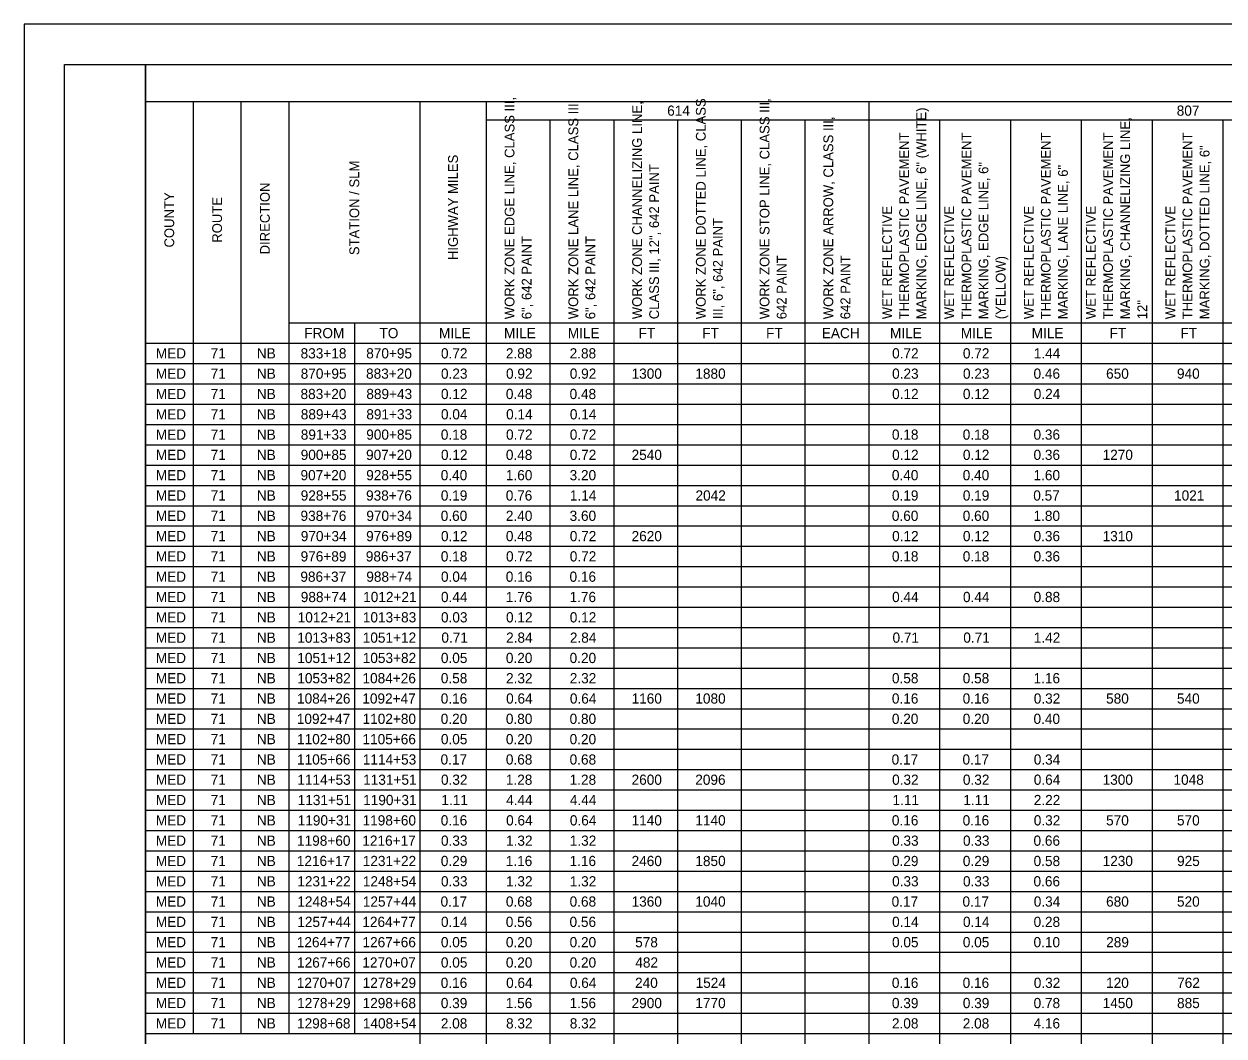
# Model space of a CAD drawing. Extents: x 0 to 34, y 0 to 22.
# Drawn here: x 0 to 14.83, y 9.5 to 22 of the extents above; entities that cross this region are included whole.
import ezdxf

# ---------------------------------------------------------------- set-up
doc = ezdxf.new("R2010")
doc.units = 0
for name, color, linetype in [('SH_Border', 7, 'Continuous'), ('SH_Cut_Line', 7, 'Continuous'), ('SH_Text', 7, 'Continuous')]:
    doc.layers.add(name, color=color, linetype=linetype)

msp = doc.modelspace()

# ---------------------------------------------------------------- linework, layer by layer
at = {"layer": 'SH_Border'}
for points in [[(0.5, 21.5), (1.5, 21.5), (1.5, 0.5), (0.5, 0.5)], [(1.5, 21.5), (33.5, 21.5), (33.5, 0.5), (1.5, 0.5)]]:
    msp.add_lwpolyline(points, close=True, dxfattribs=at)
at = {"layer": 'SH_Cut_Line'}
msp.add_lwpolyline([(0, 0), (34, 0), (34, 22), (0, 22)], close=True, dxfattribs=at)
at = {"layer": 'SH_Text'}
for p, q in [((1.5, 21.5), (32, 21.5)), ((1.5, 21.5), (1.5, 0.5)), ((1.5, 21.044), (32, 21.044)), ((2.091, 21.044), (2.091, 9.529)), ((2.682, 21.044), (2.682, 9.529)), ((3.273, 21.044), (3.273, 18.308)), ((4.893, 21.044), (4.893, 0.5)), ((5.713, 21.044), (5.713, 0.5)), ((10.441, 21.044), (10.441, 0.5)), ((5.713, 20.816), (32, 20.816)), ((6.501, 20.816), (6.501, 0.5)), ((7.289, 20.816), (7.289, 0.5)), ((8.077, 20.816), (8.077, 0.5)), ((8.865, 20.816), (8.865, 0.5)), ((9.653, 20.816), (9.653, 0.5)), ((11.316, 20.816), (11.316, 0.5)), ((12.192, 20.816), (12.192, 0.5)), ((13.067, 20.816), (13.067, 0.5)), ((13.943, 20.816), (13.943, 0.5)), ((14.818, 20.816), (14.818, 0.5)), ((3.273, 18.308), (32, 18.308)), ((3.273, 18.308), (3.273, 18.057)), ((4.083, 18.308), (4.083, 9.529)), ((1.5, 18.057), (32, 18.057)), ((3.273, 18.057), (3.273, 9.529)), ((1.5, 17.806), (32, 17.806)), ((1.5, 17.555), (32, 17.555)), ((1.5, 17.305), (32, 17.305)), ((1.5, 17.054), (32, 17.054)), ((1.5, 16.803), (32, 16.803)), ((1.5, 16.552), (32, 16.552)), ((1.5, 16.301), (32, 16.301)), ((1.5, 16.05), (32, 16.05)), ((1.5, 15.8), (32, 15.8)), ((1.5, 15.549), (32, 15.549)), ((1.5, 15.298), (32, 15.298)), ((1.5, 15.047), (32, 15.047)), ((1.5, 14.796), (32, 14.796)), ((1.5, 14.546), (32, 14.546)), ((1.5, 14.295), (32, 14.295)), ((1.5, 14.044), (32, 14.044)), ((1.5, 13.793), (32, 13.793)), ((1.5, 13.542), (32, 13.542)), ((1.5, 13.292), (32, 13.292)), ((1.5, 13.041), (32, 13.041)), ((1.5, 12.79), (32, 12.79)), ((1.5, 12.539), (32, 12.539)), ((1.5, 12.288), (32, 12.288)), ((1.5, 12.037), (32, 12.037)), ((1.5, 11.787), (32, 11.787)), ((1.5, 11.536), (32, 11.536)), ((1.5, 11.285), (32, 11.285)), ((1.5, 11.034), (32, 11.034)), ((1.5, 10.783), (32, 10.783)), ((1.5, 10.533), (32, 10.533)), ((1.5, 10.282), (32, 10.282)), ((1.5, 10.031), (32, 10.031)), ((1.5, 9.78), (32, 9.78)), ((1.5, 9.529), (32, 9.529))]:
    msp.add_line(p, q, dxfattribs=at)

# ---------------------------------------------------------------- texts
for s, height, p in [('WORK ZONE EDGE LINE, CLASS III, ', 0.12082, (6.062, 18.353)), ('WORK ZONE DOTTED LINE, CLASS ', 0.12082, (8.426, 18.353)), ('WORK ZONE STOP LINE, CLASS III, ', 0.12082, (9.214, 18.353)), ('WORK ZONE LANE LINE, CLASS III, ', 0.12082, (6.85, 18.353)), ('WORK ZONE CHANNELIZING LINE, ', 0.12082, (7.638, 18.353)), ('MARKING, EDGE LINE, 6" (WHITE)', 0.12082, (11.151, 18.353)), ('WORK ZONE ARROW, CLASS III, ', 0.12082, (10.002, 18.353)), ('MARKING, CHANNELIZING LINE, ', 0.12082, (13.671, 18.353)), ('THERMOPLASTIC PAVEMENT ', 0.12082, (10.939, 18.353)), ('THERMOPLASTIC PAVEMENT ', 0.12082, (11.709, 18.353)), ('THERMOPLASTIC PAVEMENT ', 0.12082, (12.69, 18.353)), ('THERMOPLASTIC PAVEMENT ', 0.12082, (13.46, 18.353)), ('THERMOPLASTIC PAVEMENT ', 0.12082, (14.441, 18.353)), ('MARKING, DOTTED LINE, 6"', 0.12082, (14.653, 18.353)), ('HIGHWAY MILES', 0.12082, (5.363, 19.084)), ('STATION / SLM', 0.12082, (4.143, 19.145)), ('CLASS III, 12", 642 PAINT', 0.12082, (7.849, 18.353)), ('MARKING, EDGE LINE, 6" ', 0.12082, (11.92, 18.353)), ('MARKING, LANE LINE, 6"', 0.12082, (12.902, 18.353)), ('DIRECTION', 0.1208, (3.038, 19.154)), ('COUNTY', 0.1208, (1.856, 19.239)), ('ROUTE', 0.1208, (2.447, 19.298)), ('WET REFLECTIVE ', 0.12082, (10.728, 18.353)), ('WET REFLECTIVE ', 0.12082, (11.497, 18.353)), ('WET REFLECTIVE ', 0.12082, (12.479, 18.353)), ('WET REFLECTIVE ', 0.12082, (13.248, 18.353)), ('WET REFLECTIVE ', 0.12082, (14.23, 18.353)), ('III, 6", 642 PAINT', 0.12082, (8.637, 18.353)), ('6", 642 PAINT', 0.12082, (6.273, 18.353)), ('6", 642 PAINT', 0.12082, (7.061, 18.353)), ('642 PAINT', 0.1208, (9.425, 18.353)), ('642 PAINT', 0.1208, (10.213, 18.353)), ('(YELLOW)', 0.1208, (12.132, 18.353)), ('12"', 0.1208, (13.883, 18.353))]:
    msp.add_text(s, height=height, rotation=90, dxfattribs=at).set_placement(p)
for s, p in [('614', (7.95, 20.867)), ('807', (14.248, 20.867)), ('FROM', (3.464, 18.119)), ('TO', (4.394, 18.119)), ('MILE', (5.129, 18.119)), ('MILE', (5.933, 18.119)), ('MILE', (6.721, 18.119)), ('FT', (7.596, 18.119)), ('FT', (8.384, 18.119)), ('FT', (9.172, 18.119)), ('EACH', (9.861, 18.119)), ('MILE', (10.704, 18.119)), ('MILE', (11.58, 18.119)), ('MILE', (12.455, 18.119)), ('FT', (13.418, 18.119)), ('FT', (14.294, 18.119)), ('MED', (1.629, 17.869)), ('71', (2.307, 17.869)), ('NB', (2.878, 17.869)), ('833+18', (3.419, 17.869)), ('870+95', (4.23, 17.869)), ('0.72', (5.154, 17.869)), ('2.88', (5.956, 17.869)), ('2.88', (6.744, 17.869)), ('0.72', (10.73, 17.869)), ('0.72', (11.605, 17.869)), ('1.44', (12.481, 17.869)), ('MED', (1.629, 17.618)), ('71', (2.307, 17.618)), ('NB', (2.878, 17.618)), ('870+95', (3.42, 17.618)), ('883+20', (4.228, 17.618)), ('0.23', (5.154, 17.618)), ('0.92', (5.958, 17.618)), ('0.92', (6.746, 17.618)), ('1300', (7.51, 17.618)), ('1880', (8.298, 17.618)), ('0.23', (10.73, 17.618)), ('0.23', (11.606, 17.618)), ('0.46', (12.478, 17.618)), ('650', (13.375, 17.618)), ('940', (14.251, 17.618)), ('MED', (1.629, 17.367)), ('71', (2.307, 17.367)), ('NB', (2.878, 17.367)), ('883+20', (3.418, 17.367)), ('889+43', (4.231, 17.367)), ('0.12', (5.154, 17.367)), ('0.48', (5.956, 17.367)), ('0.48', (6.744, 17.367)), ('0.12', (10.73, 17.367)), ('0.12', (11.605, 17.367)), ('0.24', (12.481, 17.367)), ('MED', (1.629, 17.116)), ('71', (2.307, 17.116)), ('NB', (2.878, 17.116)), ('889+43', (3.421, 17.116)), ('891+33', (4.231, 17.116)), ('0.04', (5.154, 17.116)), ('0.14', (5.959, 17.116)), ('0.14', (6.747, 17.116)), ('MED', (1.629, 16.865)), ('71', (2.307, 16.865)), ('NB', (2.878, 16.865)), ('891+33', (3.421, 16.865)), ('900+85', (4.23, 16.865)), ('0.18', (5.152, 16.865)), ('0.72', (5.958, 16.865)), ('0.72', (6.746, 16.865)), ('0.18', (10.728, 16.865)), ('0.18', (11.603, 16.865)), ('0.36', (12.478, 16.865)), ('MED', (1.629, 16.615)), ('71', (2.307, 16.615)), ('NB', (2.878, 16.615)), ('900+85', (3.42, 16.615)), ('907+20', (4.228, 16.615)), ('0.12', (5.154, 16.615)), ('0.48', (5.956, 16.615)), ('0.72', (6.746, 16.615)), ('2540', (7.51, 16.615)), ('0.12', (10.73, 16.615)), ('0.12', (11.605, 16.615)), ('0.36', (12.478, 16.615)), ('1270', (13.332, 16.615)), ('MED', (1.629, 16.364)), ('71', (2.307, 16.364)), ('NB', (2.878, 16.364)), ('907+20', (3.418, 16.364)), ('928+55', (4.23, 16.364)), ('0.40', (5.151, 16.364)), ('1.60', (5.956, 16.364)), ('3.20', (6.744, 16.364)), ('0.40', (10.727, 16.364)), ('0.40', (11.603, 16.364)), ('1.60', (12.478, 16.364)), ('MED', (1.629, 16.113)), ('71', (2.307, 16.113)), ('NB', (2.878, 16.113)), ('928+55', (3.42, 16.113)), ('938+76', (4.228, 16.113)), ('0.19', (5.152, 16.113)), ('0.76', (5.955, 16.113)), ('1.14', (6.747, 16.113)), ('2042', (8.3, 16.113)), ('0.19', (10.728, 16.113)), ('0.19', (11.604, 16.113)), ('0.57', (12.475, 16.113)), ('1021', (14.215, 16.113)), ('MED', (1.629, 15.862)), ('71', (2.307, 15.862)), ('NB', (2.878, 15.862)), ('938+76', (3.418, 15.862)), ('970+34', (4.231, 15.862)), ('0.60', (5.151, 15.862)), ('2.40', (5.956, 15.862)), ('3.60', (6.744, 15.862)), ('0.60', (10.727, 15.862)), ('0.60', (11.603, 15.862)), ('1.80', (12.478, 15.862)), ('MED', (1.629, 15.611)), ('71', (2.307, 15.611)), ('NB', (2.878, 15.611)), ('970+34', (3.421, 15.611)), ('976+89', (4.229, 15.611)), ('0.12', (5.154, 15.611)), ('0.48', (5.956, 15.611)), ('0.72', (6.746, 15.611)), ('2620', (7.51, 15.611)), ('0.12', (10.73, 15.611)), ('0.12', (11.605, 15.611)), ('0.36', (12.478, 15.611)), ('1310', (13.332, 15.611)), ('MED', (1.629, 15.361)), ('71', (2.307, 15.361)), ('NB', (2.878, 15.361)), ('976+89', (3.419, 15.361)), ('986+37', (4.225, 15.361)), ('0.18', (5.152, 15.361)), ('0.72', (5.958, 15.361)), ('0.72', (6.746, 15.361)), ('0.18', (10.728, 15.361)), ('0.18', (11.603, 15.361)), ('0.36', (12.478, 15.361)), ('MED', (1.629, 15.11)), ('71', (2.307, 15.11)), ('NB', (2.878, 15.11)), ('986+37', (3.416, 15.11)), ('988+74', (4.231, 15.11)), ('0.04', (5.154, 15.11)), ('0.16', (5.955, 15.11)), ('0.16', (6.743, 15.11)), ('MED', (1.629, 14.859)), ('71', (2.307, 14.859)), ('NB', (2.878, 14.859)), ('988+74', (3.421, 14.859)), ('1012+21', (4.192, 14.859)), ('0.44', (5.154, 14.859)), ('1.76', (5.955, 14.859)), ('1.76', (6.743, 14.859)), ('0.44', (10.73, 14.859)), ('0.44', (11.606, 14.859)), ('0.88', (12.479, 14.859)), ('MED', (1.629, 14.608)), ('71', (2.307, 14.608)), ('NB', (2.878, 14.608)), ('1012+21', (3.383, 14.608)), ('1013+83', (4.188, 14.608)), ('0.03', (5.154, 14.608)), ('0.12', (5.958, 14.608)), ('0.12', (6.746, 14.608)), ('MED', (1.629, 14.357)), ('71', (2.307, 14.357)), ('NB', (2.878, 14.357)), ('1013+83', (3.378, 14.357)), ('1051+12', (4.187, 14.357)), ('0.71', (5.159, 14.357)), ('2.84', (5.959, 14.357)), ('2.84', (6.747, 14.357)), ('0.71', (10.735, 14.357)), ('0.71', (11.61, 14.357)), ('1.42', (12.481, 14.357)), ('MED', (1.629, 14.106)), ('71', (2.307, 14.106)), ('NB', (2.878, 14.106)), ('1051+12', (3.378, 14.106)), ('1053+82', (4.187, 14.106)), ('0.05', (5.153, 14.106)), ('0.20', (5.956, 14.106)), ('0.20', (6.744, 14.106)), ('MED', (1.629, 13.856)), ('71', (2.307, 13.856)), ('NB', (2.878, 13.856)), ('1053+82', (3.378, 13.856)), ('1084+26', (4.184, 13.856)), ('0.58', (5.152, 13.856)), ('2.32', (5.958, 13.856)), ('2.32', (6.746, 13.856)), ('0.58', (10.728, 13.856)), ('0.58', (11.603, 13.856)), ('1.16', (12.478, 13.856)), ('MED', (1.629, 13.605)), ('71', (2.307, 13.605)), ('NB', (2.878, 13.605)), ('1084+26', (3.375, 13.605)), ('1092+47', (4.182, 13.605)), ('0.16', (5.151, 13.605)), ('0.64', (5.959, 13.605)), ('0.64', (6.747, 13.605)), ('1160', (7.51, 13.605)), ('1080', (8.298, 13.605)), ('0.16', (10.727, 13.605)), ('0.16', (11.602, 13.605)), ('0.32', (12.481, 13.605)), ('580', (13.375, 13.605)), ('540', (14.251, 13.605)), ('MED', (1.629, 13.354)), ('71', (2.307, 13.354)), ('NB', (2.878, 13.354)), ('1092+47', (3.372, 13.354)), ('1102+80', (4.185, 13.354)), ('0.20', (5.151, 13.354)), ('0.80', (5.956, 13.354)), ('0.80', (6.744, 13.354)), ('0.20', (10.727, 13.354)), ('0.20', (11.603, 13.354)), ('0.40', (12.478, 13.354)), ('MED', (1.629, 13.103)), ('71', (2.307, 13.103)), ('NB', (2.878, 13.103)), ('1102+80', (3.375, 13.103)), ('1105+66', (4.184, 13.103)), ('0.05', (5.153, 13.103)), ('0.20', (5.956, 13.103)), ('0.20', (6.744, 13.103)), ('MED', (1.629, 12.852)), ('71', (2.307, 12.852)), ('NB', (2.878, 12.852)), ('1105+66', (3.375, 12.852)), ('1114+53', (4.188, 12.852)), ('0.17', (5.149, 12.852)), ('0.68', (5.956, 12.852)), ('0.68', (6.744, 12.852)), ('0.17', (10.724, 12.852)), ('0.17', (11.6, 12.852)), ('0.34', (12.481, 12.852)), ('MED', (1.629, 12.602)), ('71', (2.307, 12.602)), ('NB', (2.878, 12.602)), ('1114+53', (3.378, 12.602)), ('1131+51', (4.192, 12.602)), ('0.32', (5.154, 12.602)), ('1.28', (5.956, 12.602)), ('1.28', (6.744, 12.602)), ('2600', (7.51, 12.602)), ('2096', (8.297, 12.602)), ('0.32', (10.73, 12.602)), ('0.32', (11.605, 12.602)), ('0.64', (12.481, 12.602)), ('1300', (13.332, 12.602)), ('1048', (14.208, 12.602)), ('MED', (1.629, 12.351)), ('71', (2.307, 12.351)), ('NB', (2.878, 12.351)), ('1131+51', (3.383, 12.351)), ('1190+31', (4.192, 12.351)), ('1.11', (5.159, 12.351)), ('4.44', (5.959, 12.351)), ('4.44', (6.747, 12.351)), ('1.11', (10.735, 12.351)), ('1.11', (11.61, 12.351)), ('2.22', (12.481, 12.351)), ('MED', (1.629, 12.1)), ('71', (2.307, 12.1)), ('NB', (2.878, 12.1)), ('1190+31', (3.383, 12.1)), ('1198+60', (4.185, 12.1)), ('0.16', (5.151, 12.1)), ('0.64', (5.959, 12.1)), ('0.64', (6.747, 12.1)), ('1140', (7.51, 12.1)), ('1140', (8.298, 12.1)), ('0.16', (10.727, 12.1)), ('0.16', (11.602, 12.1)), ('0.32', (12.481, 12.1)), ('570', (13.375, 12.1)), ('570', (14.251, 12.1)), ('MED', (1.629, 11.849)), ('71', (2.307, 11.849)), ('NB', (2.878, 11.849)), ('1198+60', (3.375, 11.849)), ('1216+17', (4.182, 11.849)), ('0.33', (5.154, 11.849)), ('1.32', (5.958, 11.849)), ('1.32', (6.746, 11.849)), ('0.33', (10.73, 11.849)), ('0.33', (11.606, 11.849)), ('0.66', (12.478, 11.849)), ('MED', (1.629, 11.598)), ('71', (2.307, 11.598)), ('NB', (2.878, 11.598)), ('1216+17', (3.372, 11.598)), ('1231+22', (4.187, 11.598)), ('0.29', (5.152, 11.598)), ('1.16', (5.955, 11.598)), ('1.16', (6.743, 11.598)), ('2460', (7.51, 11.598)), ('1850', (8.298, 11.598)), ('0.29', (10.728, 11.598)), ('0.29', (11.604, 11.598)), ('0.58', (12.479, 11.598)), ('1230', (13.332, 11.598)), ('925', (14.252, 11.598)), ('MED', (1.629, 11.347)), ('71', (2.307, 11.347)), ('NB', (2.878, 11.347)), ('1231+22', (3.378, 11.347)), ('1248+54', (4.188, 11.347)), ('0.33', (5.154, 11.347)), ('1.32', (5.958, 11.347)), ('1.32', (6.746, 11.347)), ('0.33', (10.73, 11.347)), ('0.33', (11.606, 11.347)), ('0.66', (12.478, 11.347)), ('MED', (1.629, 11.097)), ('71', (2.307, 11.097)), ('NB', (2.878, 11.097)), ('1248+54', (3.378, 11.097)), ('1257+44', (4.188, 11.097)), ('0.17', (5.149, 11.097)), ('0.68', (5.956, 11.097)), ('0.68', (6.744, 11.097)), ('1360', (7.51, 11.097)), ('1040', (8.298, 11.097)), ('0.17', (10.724, 11.097)), ('0.17', (11.6, 11.097)), ('0.34', (12.481, 11.097)), ('680', (13.375, 11.097)), ('520', (14.251, 11.097)), ('MED', (1.629, 10.846)), ('71', (2.307, 10.846)), ('NB', (2.878, 10.846)), ('1257+44', (3.378, 10.846)), ('1264+77', (4.182, 10.846)), ('0.14', (5.154, 10.846)), ('0.56', (5.955, 10.846)), ('0.56', (6.743, 10.846)), ('0.14', (10.73, 10.846)), ('0.14', (11.606, 10.846)), ('0.28', (12.479, 10.846)), ('MED', (1.629, 10.595)), ('71', (2.307, 10.595)), ('NB', (2.878, 10.595)), ('1264+77', (3.372, 10.595)), ('1267+66', (4.184, 10.595)), ('0.05', (5.153, 10.595)), ('0.20', (5.956, 10.595)), ('0.20', (6.744, 10.595)), ('578', (7.554, 10.595)), ('0.05', (10.729, 10.595)), ('0.05', (11.604, 10.595)), ('0.10', (12.478, 10.595)), ('289', (13.376, 10.595)), ('MED', (1.629, 10.344)), ('71', (2.307, 10.344)), ('NB', (2.878, 10.344)), ('1267+66', (3.375, 10.344)), ('1270+07', (4.182, 10.344)), ('0.05', (5.153, 10.344)), ('0.20', (5.956, 10.344)), ('0.20', (6.744, 10.344)), ('482', (7.556, 10.344)), ('MED', (1.629, 10.093)), ('71', (2.307, 10.093)), ('NB', (2.878, 10.093)), ('1270+07', (3.372, 10.093)), ('1278+29', (4.186, 10.093)), ('0.16', (5.151, 10.093)), ('0.64', (5.959, 10.093)), ('0.64', (6.747, 10.093)), ('240', (7.553, 10.093)), ('1524', (8.301, 10.093)), ('0.16', (10.727, 10.093)), ('0.16', (11.602, 10.093)), ('0.32', (12.481, 10.093)), ('120', (13.375, 10.093)), ('762', (14.253, 10.093)), ('MED', (1.629, 9.843)), ('71', (2.307, 9.843)), ('NB', (2.878, 9.843)), ('1278+29', (3.376, 9.843)), ('1298+68', (4.185, 9.843)), ('0.39', (5.152, 9.843)), ('1.56', (5.955, 9.843)), ('1.56', (6.743, 9.843)), ('2900', (7.51, 9.843)), ('1770', (8.298, 9.843)), ('0.39', (10.728, 9.843)), ('0.39', (11.604, 9.843)), ('0.78', (12.479, 9.843)), ('1450', (13.332, 9.843)), ('885', (14.252, 9.843)), ('MED', (1.629, 9.592)), ('71', (2.307, 9.592)), ('NB', (2.878, 9.592)), ('1298+68', (3.375, 9.592)), ('1408+54', (4.188, 9.592)), ('2.08', (5.152, 9.592)), ('8.32', (5.958, 9.592)), ('8.32', (6.746, 9.592)), ('2.08', (10.728, 9.592)), ('2.08', (11.603, 9.592)), ('4.16', (12.478, 9.592))]:
    msp.add_text(s, height=0.1259, dxfattribs=at).set_placement(p)

doc.saveas('drawing.dxf')
